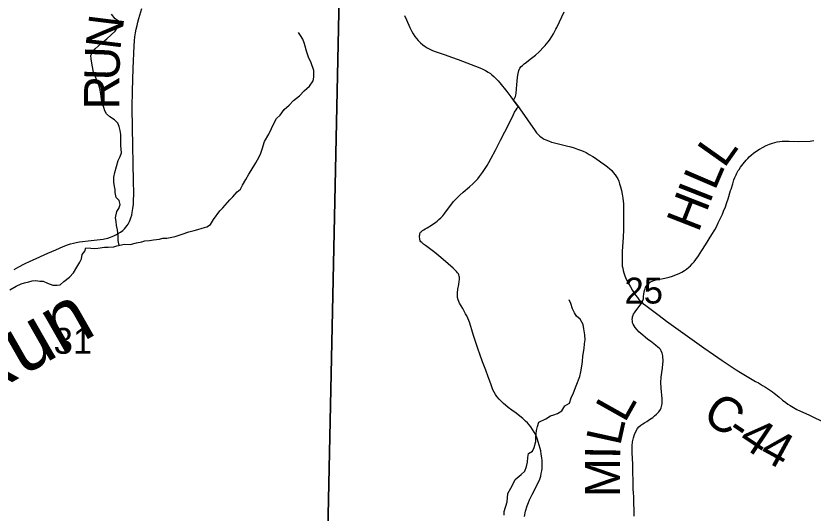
# Model space of a CAD drawing. Extents: x -1.2 to 34, y -8.5 to 22.
# Drawn here: x 5.742 to 7.031, y 14.804 to 15.609 of the extents above; entities that cross this region are included whole.
import ezdxf

# ---------------------------------------------------------------- set-up
doc = ezdxf.new("R2010")
doc.units = 0
for name, color, linetype in [('GM_X_County_Road', 7, 'Continuous'), ('GM_X_County_Road_Text', 7, 'Continuous'), ('GM_X_Minor_River', 7, 'Continuous'), ('GM_X_Minor_River_Text', 7, 'Continuous'), ('GM_X_Section', 7, 'Continuous'), ('GM_X_Section_Text', 7, 'Continuous'), ('GM_X_Township_Road', 7, 'Continuous'), ('GM_X_Township_Road_Text', 7, 'Continuous')]:
    doc.layers.add(name, color=color, linetype=linetype)

msp = doc.modelspace()

# ---------------------------------------------------------------- linework, layer by layer
at = {"layer": 'GM_X_County_Road'}
for points in [[(5.7397, 15.1987), (5.7472, 15.2028), (5.7563, 15.2075), (5.7654, 15.2117), (5.7737, 15.2155), (5.782, 15.2193), (5.794, 15.2248), (5.8067, 15.2305), (5.8188, 15.2357), (5.8257, 15.2384), (5.8304, 15.24), (5.8351, 15.2413), (5.8395, 15.2423), (5.8452, 15.2431), (5.8641, 15.2454), (5.8834, 15.2478), (5.8856, 15.2482), (5.8907, 15.2494), (5.8954, 15.2509), (5.9003, 15.2528), (5.9049, 15.2549), (5.9078, 15.2566), (5.9116, 15.2591), (5.9151, 15.2618), (5.918, 15.2645), (5.9201, 15.2667), (5.9222, 15.2696), (5.9238, 15.272), (5.9259, 15.276), (5.9271, 15.279), (5.9283, 15.2823), (5.9294, 15.2865), (5.9303, 15.2909), (5.9312, 15.2969), (5.9321, 15.3042), (5.9324, 15.3086), (5.9327, 15.3219), (5.9324, 15.3415), (5.9308, 15.4276), (5.9302, 15.4605), (5.9307, 15.4876), (5.9319, 15.5238), (5.9332, 15.5606), (5.9339, 15.5683), (5.9346, 15.5748), (5.9356, 15.5816), (5.9368, 15.5875), (5.9382, 15.5934), (5.9396, 15.5988), (5.9412, 15.6048), (5.9458, 15.6207)], [(6.3704, 15.6092), (6.3735, 15.6023), (6.3789, 15.5898), (6.3822, 15.5834), (6.3845, 15.5796), (6.3871, 15.5757), (6.3897, 15.5722), (6.3927, 15.5691), (6.3965, 15.5653), (6.4003, 15.5622), (6.4038, 15.5595), (6.4071, 15.5573), (6.4114, 15.5549), (6.4159, 15.5527), (6.42, 15.5511), (6.4266, 15.5488), (6.4361, 15.5457), (6.4464, 15.5422), (6.4573, 15.538), (6.492, 15.5247), (6.4973, 15.5224), (6.5015, 15.5203), (6.5058, 15.5179), (6.5095, 15.5154), (6.5119, 15.5135), (6.5149, 15.5108), (6.5186, 15.5072), (6.5217, 15.5039), (6.5245, 15.5006), (6.5359, 15.4864), (6.5425, 15.4776), (6.5451, 15.4741), (6.546, 15.4729)], [(6.546, 15.4729), (6.5494, 15.4685), (6.5545, 15.4616)], [(6.5545, 15.4616), (6.5567, 15.4586), (6.5815, 15.4228), (6.5839, 15.4196), (6.5869, 15.4164), (6.5893, 15.4142), (6.5929, 15.4114), (6.5963, 15.4095), (6.5992, 15.408), (6.6031, 15.4064), (6.6081, 15.4046), (6.6107, 15.4039), (6.6323, 15.3984), (6.6395, 15.3967), (6.6447, 15.3952), (6.6503, 15.3934), (6.6549, 15.3917), (6.6593, 15.3898), (6.6641, 15.3875), (6.6692, 15.3848), (6.6747, 15.3814), (6.6791, 15.3786), (6.6874, 15.3726), (6.6941, 15.3678), (6.6988, 15.3644), (6.7026, 15.3612), (6.7054, 15.3586), (6.708, 15.3554), (6.7108, 15.3518), (6.7133, 15.3484), (6.7152, 15.3451), (6.7168, 15.3412), (6.7183, 15.3371), (6.7199, 15.3321), (6.7215, 15.3262), (6.7226, 15.3201), (6.7235, 15.314), (6.7244, 15.3046), (6.7247, 15.2892), (6.7246, 15.2792), (6.7243, 15.2627), (6.7238, 15.2506), (6.7225, 15.2278), (6.7221, 15.2149), (6.7223, 15.2087), (6.7226, 15.204), (6.7232, 15.2007), (6.7239, 15.1968), (6.7249, 15.1929), (6.7266, 15.1883), (6.729, 15.1827), (6.7323, 15.1767), (6.736, 15.1703), (6.7393, 15.1645), (6.744, 15.157), (6.747, 15.1529), (6.7492, 15.1501), (6.752, 15.1474), (6.7545, 15.1451), (6.756, 15.1437), (6.7582, 15.1419), (6.7819, 15.1241), (6.7942, 15.115), (6.8278, 15.0907), (6.8546, 15.0716), (6.8699, 15.0611), (6.8842, 15.0514), (6.9069, 15.036), (6.9136, 15.0317), (6.9243, 15.0254), (6.9327, 15.0206), (6.9381, 15.0175), (6.9426, 15.0149), (6.9493, 15.011), (6.9543, 15.0081), (6.9575, 15.0061), (6.9654, 15.0005), (6.968, 14.9984), (6.9756, 14.9923), (6.9818, 14.9872), (6.9867, 14.9832), (6.9902, 14.9806), (6.9939, 14.9782), (7.0019, 14.9734), (7.0045, 14.9721), (7.025, 14.9626), (7.0505, 14.9506)]]:
    msp.add_lwpolyline(points, dxfattribs=at)
at = {"layer": 'GM_X_Minor_River'}
for points in [[(5.9093, 15.2373), (5.9086, 15.2399), (5.9078, 15.2453), (5.9073, 15.2536), (5.9064, 15.2627), (5.9051, 15.2696), (5.9043, 15.276), (5.9034, 15.2821), (5.9052, 15.2924), (5.9089, 15.2974), (5.9107, 15.3039), (5.9091, 15.31), (5.9041, 15.3152), (5.9025, 15.3228), (5.9028, 15.3278), (5.9019, 15.3327), (5.9007, 15.3395), (5.9006, 15.3479), (5.902, 15.3552), (5.9078, 15.375), (5.9107, 15.3812), (5.9129, 15.3873), (5.9124, 15.393), (5.9119, 15.3991), (5.9117, 15.417), (5.9108, 15.4234), (5.9092, 15.4299), (5.9069, 15.4352), (5.9019, 15.4408), (5.8939, 15.4456), (5.8889, 15.4501), (5.8858, 15.4554), (5.8842, 15.4607), (5.8814, 15.4698), (5.8797, 15.4827), (5.8777, 15.4911), (5.8761, 15.4967), (5.8733, 15.5047), (5.8706, 15.5111), (5.8678, 15.5179), (5.8654, 15.5293), (5.8637, 15.5392), (5.8636, 15.5449), (5.8658, 15.5499), (5.8703, 15.5556), (5.8751, 15.5599), (5.8808, 15.5646), (5.8894, 15.5719), (5.8965, 15.5781), (5.9028, 15.5839), (5.9058, 15.5893), (5.9087, 15.5943), (5.9075, 15.6007), (5.9025, 15.6041), (5.8967, 15.6116)], [(5.9505, 15.2448), (5.9581, 15.2456), (5.9649, 15.2465), (5.9744, 15.2478), (5.98, 15.249), (5.9864, 15.2491), (5.9997, 15.2516), (6.0046, 15.2536), (6.011, 15.2556), (6.0219, 15.2596), (6.0302, 15.2616), (6.0362, 15.2632), (6.0434, 15.2656), (6.0509, 15.2676), (6.0566, 15.2711), (6.0617, 15.2792), (6.0718, 15.2934), (6.077, 15.2984), (6.0882, 15.3112), (6.093, 15.3158), (6.0997, 15.3239), (6.1053, 15.3286), (6.1086, 15.3347), (6.1142, 15.3443), (6.1186, 15.3527), (6.1227, 15.3585), (6.1301, 15.3712), (6.1356, 15.3808), (6.1382, 15.3869), (6.1403, 15.393), (6.1439, 15.4053), (6.1513, 15.4172), (6.1554, 15.4267), (6.159, 15.4348), (6.1635, 15.4429), (6.1694, 15.4483), (6.1757, 15.4575), (6.184, 15.4645), (6.1911, 15.4718), (6.2008, 15.4792), (6.2083, 15.4873), (6.2168, 15.495), (6.2228, 15.5035), (6.2238, 15.5096), (6.2237, 15.5203), (6.2197, 15.5328), (6.215, 15.5418), (6.2119, 15.5517), (6.2098, 15.5596), (6.2083, 15.5653), (6.2063, 15.5714), (6.2024, 15.577), (6.1989, 15.5819)], [(5.7325, 15.1657), (5.7426, 15.1716), (5.7505, 15.1755), (5.7562, 15.1767), (5.763, 15.1787), (5.7686, 15.18), (5.7747, 15.1808), (5.7811, 15.1798), (5.7864, 15.1795), (5.7933, 15.1762), (5.8017, 15.1729), (5.8089, 15.173), (5.8138, 15.1738), (5.8197, 15.1788), (5.8291, 15.1858), (5.8351, 15.1928), (5.8406, 15.2024), (5.8454, 15.2101), (5.8484, 15.2158), (5.8494, 15.2227), (5.8535, 15.2281), (5.8553, 15.2334), (5.8636, 15.2332), (5.8686, 15.2325), (5.8746, 15.233), (5.8852, 15.2346), (5.8912, 15.2347), (5.9003, 15.2353), (5.9056, 15.2365), (5.9177, 15.2393), (5.9268, 15.2387), (5.937, 15.2415), (5.9456, 15.2432), (5.9505, 15.2448)], [(6.6119, 14.9631), (6.6176, 14.9655), (6.6247, 14.9698), (6.6295, 14.9779), (6.6374, 14.9822), (6.6399, 14.9906), (6.6439, 14.999), (6.648, 15.0101), (6.6538, 15.0254), (6.6556, 15.033), (6.657, 15.0418), (6.6584, 15.0495), (6.659, 15.0582), (6.6611, 15.0704), (6.6613, 15.0784), (6.6624, 15.0849), (6.6619, 15.0929), (6.6602, 15.1024), (6.6594, 15.1092), (6.6547, 15.1179), (6.6486, 15.1228), (6.6451, 15.1284), (6.642, 15.1348), (6.6392, 15.1432), (6.6367, 15.1493)], [(6.5314, 14.8009), (6.5317, 14.8067), (6.5367, 14.8227), (6.5377, 14.8361), (6.5421, 14.8449), (6.5458, 14.8506), (6.5495, 14.8587), (6.5588, 14.8668), (6.5652, 14.8722), (6.5677, 14.8795), (6.5695, 14.8868), (6.5698, 14.8944), (6.5708, 14.9005), (6.5776, 14.9044), (6.5801, 14.9105), (6.583, 14.9201), (6.5829, 14.9269), (6.5839, 14.938), (6.5853, 14.9445), (6.5875, 14.9513), (6.5991, 14.9569), (6.6063, 14.9615), (6.6119, 14.9631)]]:
    msp.add_lwpolyline(points, dxfattribs=at)
at = {"layer": 'GM_X_Section'}
for points in [[(6.2657, 15.6908), (6.2441, 14.6736), (5.4125, 14.6774), (5.4262, 15.6104), (5.428, 15.6979)], [(7.2776, 15.674), (7.2479, 14.6639), (6.2441, 14.6736), (6.2657, 15.6908)]]:
    msp.add_lwpolyline(points, close=True, dxfattribs=at)
at = {"layer": 'GM_X_Township_Road'}
for points in [[(6.6153, 15.5875), (6.6166, 15.5901), (6.6211, 15.5993), (6.6287, 15.6152)], [(6.546, 15.4729), (6.5481, 15.4752), (6.5489, 15.4762), (6.5499, 15.4783), (6.5503, 15.4803), (6.551, 15.484), (6.5514, 15.4901), (6.5521, 15.498), (6.5526, 15.5024), (6.5533, 15.5094), (6.5542, 15.5154), (6.5554, 15.5205), (6.5571, 15.5241), (6.5591, 15.5267), (6.5612, 15.5285), (6.5639, 15.5311), (6.5675, 15.534), (6.5738, 15.5389), (6.582, 15.5453), (6.5883, 15.5509), (6.5955, 15.5585), (6.5978, 15.561), (6.5997, 15.5631), (6.6032, 15.5675), (6.6058, 15.5709), (6.6087, 15.5755), (6.6112, 15.5796), (6.6126, 15.5822), (6.6153, 15.5875)], [(6.5545, 15.4616), (6.5494, 15.4685), (6.546, 15.4729)], [(6.5644, 14.799), (6.5663, 14.8073), (6.5689, 14.816), (6.5707, 14.8215), (6.5725, 14.8256), (6.5745, 14.8299), (6.5767, 14.8346), (6.5861, 14.8524), (6.589, 14.8594), (6.5906, 14.864), (6.5915, 14.8686), (6.5923, 14.8726), (6.5928, 14.8767), (6.593, 14.8819), (6.5928, 14.8896), (6.5924, 14.8939), (6.5916, 14.8994), (6.5906, 14.9053), (6.5897, 14.9087), (6.5866, 14.9197), (6.5854, 14.9232), (6.5837, 14.9281), (6.5822, 14.9313), (6.58, 14.9355), (6.5774, 14.9398), (6.5745, 14.9439), (6.5722, 14.9469), (6.5693, 14.9502), (6.5663, 14.9531), (6.5617, 14.9572), (6.5569, 14.9612), (6.5509, 14.9659), (6.5441, 14.9708), (6.5381, 14.9751), (6.534, 14.9787), (6.5306, 14.9817), (6.5274, 14.9848), (6.5233, 14.9889), (6.5198, 14.9928), (6.5174, 14.9964), (6.5154, 14.9998), (6.5135, 15.0036), (6.5103, 15.0121), (6.5082, 15.0179), (6.5055, 15.0249), (6.5019, 15.0354), (6.4988, 15.0436), (6.4967, 15.0491), (6.4922, 15.0612), (6.4894, 15.0692), (6.4872, 15.0757), (6.4846, 15.0836), (6.4821, 15.0917), (6.4795, 15.1008), (6.4777, 15.1063), (6.4755, 15.1133), (6.4745, 15.116), (6.4711, 15.1233), (6.4693, 15.1267), (6.4646, 15.1353), (6.4619, 15.1397), (6.4594, 15.1442), (6.4571, 15.1496), (6.4563, 15.1531), (6.4559, 15.1567), (6.4561, 15.1609), (6.4568, 15.1669), (6.4582, 15.1744), (6.4591, 15.1798), (6.4593, 15.1819), (6.4592, 15.1862), (6.459, 15.1876), (6.4583, 15.1898), (6.4575, 15.1915), (6.4564, 15.1933), (6.4547, 15.1954), (6.4526, 15.1976), (6.449, 15.2008), (6.4413, 15.2074), (6.4292, 15.2178), (6.4193, 15.226), (6.4107, 15.2327), (6.4044, 15.2371), (6.4011, 15.2397), (6.3984, 15.2419), (6.397, 15.2434), (6.396, 15.245), (6.3953, 15.2467), (6.395, 15.2484), (6.3946, 15.2508), (6.3948, 15.253), (6.395, 15.2545), (6.3955, 15.2566), (6.3965, 15.2586), (6.3977, 15.26), (6.3995, 15.2615), (6.4015, 15.2627), (6.4041, 15.2644), (6.4071, 15.2659), (6.4143, 15.2701), (6.4209, 15.275), (6.423, 15.2766), (6.426, 15.2792), (6.4293, 15.2822), (6.4324, 15.2855), (6.4357, 15.2895), (6.4498, 15.3083), (6.4546, 15.3133), (6.46, 15.3188), (6.4655, 15.3235), (6.4758, 15.3323), (6.4812, 15.3376), (6.4848, 15.341), (6.4888, 15.3452), (6.4918, 15.349), (6.4964, 15.3553), (6.5042, 15.367), (6.5069, 15.3714), (6.5108, 15.3787), (6.5174, 15.3915), (6.5217, 15.4001), (6.5256, 15.4076), (6.5326, 15.4211), (6.5451, 15.4457), (6.5485, 15.4529), (6.5508, 15.457), (6.5526, 15.4595), (6.5545, 15.4616)], [(6.7545, 15.1451), (6.755, 15.1462), (6.7558, 15.1483), (6.7566, 15.1511), (6.7571, 15.1546), (6.7576, 15.159), (6.7587, 15.1645), (6.7594, 15.1674), (6.7603, 15.1695), (6.7614, 15.172), (6.7632, 15.1742), (6.7645, 15.1756), (6.7665, 15.1773), (6.7683, 15.1785), (6.7706, 15.1796), (6.7736, 15.1808), (6.7775, 15.1819), (6.7831, 15.183), (6.7915, 15.1846), (6.7981, 15.1862), (6.8036, 15.1878), (6.8075, 15.1891), (6.8146, 15.1921), (6.8189, 15.1942), (6.8232, 15.1967), (6.8266, 15.1991), (6.8303, 15.2021), (6.8326, 15.2043), (6.8357, 15.2076), (6.8385, 15.2109), (6.8415, 15.2149), (6.8456, 15.2207), (6.851, 15.2292), (6.8568, 15.2382), (6.8675, 15.2551), (6.8722, 15.2629), (6.8747, 15.2675), (6.8778, 15.2737), (6.8846, 15.2882), (6.8864, 15.2926), (6.8892, 15.2999), (6.8915, 15.3066), (6.8935, 15.3129), (6.8975, 15.3261), (6.8983, 15.3284), (6.901, 15.337), (6.9031, 15.3433), (6.9047, 15.3472), (6.9065, 15.3515), (6.9074, 15.3535), (6.9101, 15.3585), (6.9114, 15.3605), (6.9136, 15.3639), (6.9159, 15.367), (6.9179, 15.3695), (6.9227, 15.3752), (6.9253, 15.378), (6.9278, 15.3805), (6.9309, 15.3834), (6.9347, 15.3865), (6.9398, 15.3902), (6.9445, 15.3933), (6.9501, 15.3966), (6.9554, 15.3993), (6.9605, 15.4015), (6.9652, 15.4031), (6.969, 15.4042), (6.9731, 15.4051), (6.9771, 15.4057), (6.9812, 15.4061), (6.9851, 15.4063), (6.9924, 15.4061), (7.0077, 15.4056), (7.0261, 15.4061), (7.0289, 15.4064), (7.032, 15.407)], [(6.7418, 14.7996), (6.7417, 14.8065), (6.7414, 14.8232), (6.7411, 14.8311), (6.7407, 14.8368), (6.7402, 14.8436), (6.7399, 14.8583), (6.7398, 14.8688), (6.7394, 14.8834), (6.7385, 14.9017), (6.7384, 14.9132), (6.739, 14.9194), (6.7407, 14.926), (6.7425, 14.9317), (6.745, 14.9374), (6.7471, 14.9412), (6.7494, 14.9437), (6.7525, 14.9465), (6.7559, 14.949), (6.7583, 14.9504), (6.7622, 14.9527), (6.7668, 14.9557), (6.7717, 14.9592), (6.7746, 14.9617), (6.7777, 14.9643), (6.7814, 14.9684), (6.7841, 14.972), (6.7854, 14.9747), (6.7861, 14.9769), (6.7864, 14.9792), (6.7868, 14.9817), (6.787, 14.9851), (6.7869, 14.989), (6.7855, 15.0062), (6.7851, 15.0155), (6.7852, 15.0242), (6.7863, 15.0318), (6.7873, 15.0386), (6.7882, 15.0456), (6.7884, 15.0497), (6.788, 15.0588), (6.787, 15.0629), (6.7854, 15.0669), (6.7842, 15.0688), (6.7822, 15.0711), (6.7801, 15.073), (6.7761, 15.0762), (6.7683, 15.0824), (6.7641, 15.0854), (6.7596, 15.089), (6.7558, 15.0921), (6.7525, 15.0951), (6.7495, 15.0978), (6.7464, 15.101), (6.7436, 15.1044), (6.7416, 15.1073), (6.7402, 15.1099), (6.7393, 15.1124), (6.7388, 15.1153), (6.7386, 15.1174), (6.7388, 15.12), (6.7391, 15.122), (6.7401, 15.1247), (6.7408, 15.1262), (6.7422, 15.1285), (6.7445, 15.1318), (6.75, 15.1388), (6.7525, 15.1423), (6.7545, 15.1451)]]:
    msp.add_lwpolyline(points, dxfattribs=at)

# ---------------------------------------------------------------- texts
at = {"layer": 'GM_X_County_Road_Text'}
for s, rotation, p in [('N', 82.9111, (5.9109, 15.5521)), ('U', 87.9815, (5.9092, 15.5035)), ('R', 89.9063, (5.9092, 15.4573)), ('C', 325.8163, (6.8494, 14.9566)), ('-', 325.8702, (6.888, 14.9304)), ('4', 326.0756, (6.9075, 14.9172)), ('4', 331.4263, (6.9415, 14.8946))]:
    msp.add_text(s, height=0.0568, rotation=rotation, dxfattribs=at).set_placement(p)
at = {"layer": 'GM_X_Minor_River_Text'}
msp.add_text('Run', height=0.09469, rotation=29.6968, dxfattribs=at).set_placement((5.6736, 14.9804))
at = {"layer": 'GM_X_Section_Text'}
for s, p in [('25', (6.7261, 15.1434)), ('31', (5.8032, 15.0621))]:
    msp.add_text(s, height=0.04186, rotation=0, dxfattribs=at).set_placement(p)
at = {"layer": 'GM_X_Township_Road_Text'}
for s, rotation, p in [('L', 54.7134, (6.8873, 15.3612)), ('L', 66.766, (6.8721, 15.3249)), ('I', 68.5421, (6.8637, 15.3036)), ('H', 68.6471, (6.8455, 15.257)), ('L', 60.6394, (6.7266, 14.9491)), ('L', 77.626, (6.719, 14.9118)), ('I', 89.1647, (6.719, 14.8914)), ('M', 89.9675, (6.719, 14.83))]:
    msp.add_text(s, height=0.0568, rotation=rotation, dxfattribs=at).set_placement(p)

doc.saveas('drawing.dxf')
